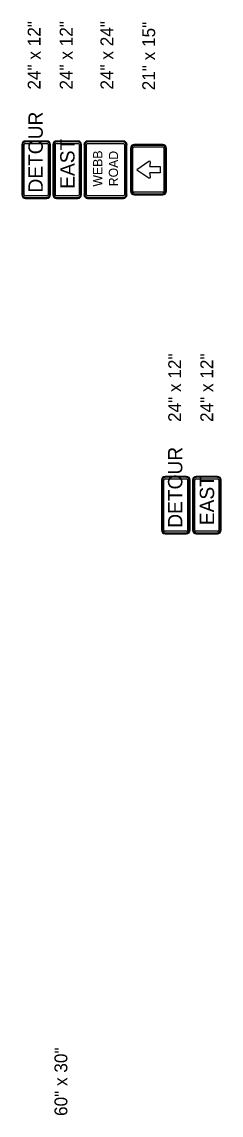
# Model space of a CAD drawing. Extents: x 1123038 to 1172987, y 554419 to 623636.
# Drawn here: x 1145939 to 1147850, y 566289 to 576781 of the extents above; entities that cross this region are included whole.
import ezdxf

# ---------------------------------------------------------------- set-up
doc = ezdxf.new("R2010")
doc.units = 0
doc.layers.add('D_Text_Standard', color=7, linetype='Continuous')
doc.layers.add('Default', color=7, linetype='Continuous')

msp = doc.modelspace()

# ---------------------------------------------------------------- linework, layer by layer
at = {"layer": 'Default'}
for p, q in [((1145939, 575603), (1145939, 575122)), ((1145947, 575603), (1145947, 575122)), ((1145962, 575122), (1145962, 575603)), ((1146179, 575637), (1145973, 575637)), ((1146179, 575629), (1145973, 575629)), ((1145973, 575614), (1146179, 575614)), ((1146191, 575603), (1146191, 575122)), ((1146205, 575122), (1146205, 575603)), ((1146214, 575122), (1146214, 575603)), ((1146237, 575603), (1146237, 575122)), ((1146245, 575603), (1146245, 575122)), ((1146260, 575122), (1146260, 575603)), ((1146477, 575637), (1146271, 575637)), ((1146477, 575629), (1146271, 575629)), ((1146271, 575614), (1146477, 575614)), ((1146489, 575603), (1146489, 575122)), ((1146503, 575122), (1146503, 575603)), ((1146512, 575122), (1146512, 575603)), ((1146535, 575603), (1146535, 575122)), ((1146543, 575603), (1146543, 575122)), ((1146558, 575122), (1146558, 575603)), ((1146913, 575637), (1146569, 575637)), ((1146913, 575629), (1146569, 575629)), ((1146569, 575614), (1146913, 575614)), ((1146924, 575603), (1146924, 575122)), ((1146938, 575122), (1146938, 575603)), ((1146947, 575122), (1146947, 575603)), ((1147291, 575603), (1147016, 575603)), ((1147291, 575594), (1147016, 575594)), ((1146981, 575569), (1146981, 575156)), ((1146990, 575569), (1146990, 575156)), ((1147004, 575156), (1147004, 575569)), ((1147016, 575580), (1147291, 575580)), ((1147302, 575569), (1147302, 575156)), ((1147317, 575156), (1147317, 575569)), ((1147325, 575156), (1147325, 575569)), ((1147156, 575441), (1147042, 575362)), ((1147165, 575392), (1147173, 575429)), ((1147165, 575392), (1147265, 575392)), ((1147265, 575392), (1147265, 575332)), ((1147042, 575362), (1147156, 575284)), ((1147173, 575296), (1147165, 575332)), ((1147265, 575332), (1147165, 575332)), ((1146179, 575110), (1145973, 575110)), ((1145973, 575096), (1146179, 575096)), ((1145973, 575087), (1146179, 575087)), ((1146477, 575110), (1146271, 575110)), ((1146271, 575096), (1146477, 575096)), ((1146271, 575087), (1146477, 575087)), ((1146913, 575110), (1146569, 575110)), ((1146569, 575096), (1146913, 575096)), ((1146569, 575087), (1146913, 575087)), ((1147291, 575145), (1147016, 575145)), ((1147016, 575130), (1147291, 575130)), ((1147016, 575122), (1147291, 575122)), ((1147277, 572384), (1147277, 571903)), ((1147286, 572384), (1147286, 571903)), ((1147300, 571903), (1147300, 572384)), ((1147518, 572419), (1147312, 572419)), ((1147518, 572410), (1147312, 572410)), ((1147312, 572396), (1147518, 572396)), ((1147529, 572384), (1147529, 571903)), ((1147544, 571903), (1147544, 572384)), ((1147552, 571903), (1147552, 572384)), ((1147575, 572384), (1147575, 571903)), ((1147584, 572384), (1147584, 571903)), ((1147598, 571903), (1147598, 572384)), ((1147816, 572419), (1147610, 572419)), ((1147816, 572410), (1147610, 572410)), ((1147610, 572396), (1147816, 572396)), ((1147827, 572384), (1147827, 571903)), ((1147842, 571903), (1147842, 572384)), ((1147850, 571903), (1147850, 572384)), ((1147518, 571892), (1147312, 571892)), ((1147312, 571877), (1147518, 571877)), ((1147312, 571869), (1147518, 571869)), ((1147816, 571892), (1147610, 571892)), ((1147610, 571877), (1147816, 571877)), ((1147610, 571869), (1147816, 571869))]:
    msp.add_line(p, q, dxfattribs=at)
for centre, radius, start, end in [((1145973, 575603), 34.4, 90, 180), ((1145973, 575603), 25.8, 90, 180), ((1145973, 575603), 11.5, 90, 180), ((1146179, 575603), 34.4, 0, 90), ((1146179, 575603), 25.8, 0, 90), ((1146179, 575603), 11.5, 0, 90), ((1146271, 575603), 34.4, 90, 180), ((1146271, 575603), 25.8, 90, 180), ((1146271, 575603), 11.5, 90, 180), ((1146477, 575603), 34.4, 0, 90), ((1146477, 575603), 25.8, 0, 90), ((1146477, 575603), 11.5, 0, 90), ((1146569, 575603), 34.4, 90, 180), ((1146569, 575603), 25.8, 90, 180), ((1146569, 575603), 11.5, 90, 180), ((1146913, 575603), 34.4, 0, 90), ((1146913, 575603), 25.8, 0, 90), ((1146913, 575603), 11.5, 0, 90), ((1147016, 575569), 34.4, 90, 180), ((1147016, 575569), 25.8, 90, 180), ((1147291, 575569), 34.4, 0, 90), ((1147291, 575569), 25.8, 0, 90), ((1147016, 575569), 11.5, 90, 180), ((1147291, 575569), 11.5, 0, 90), ((1147162, 575431), 11.5, 347.0497, 122.2757), ((1147162, 575294), 11.5, 237.7244, 12.9504), ((1145973, 575122), 34.4, 180, 270), ((1145973, 575122), 25.8, 180, 270), ((1145973, 575122), 11.5, 180, 270), ((1146179, 575122), 34.4, 270, 0), ((1146179, 575122), 25.8, 270, 0), ((1146179, 575122), 11.5, 270, 0), ((1146271, 575122), 34.4, 180, 270), ((1146271, 575122), 25.8, 180, 270), ((1146271, 575122), 11.5, 180, 270), ((1146477, 575122), 34.4, 270, 0), ((1146477, 575122), 25.8, 270, 0), ((1146477, 575122), 11.5, 270, 0), ((1146569, 575122), 34.4, 180, 270), ((1146569, 575122), 25.8, 180, 270), ((1146569, 575122), 11.5, 180, 270), ((1146913, 575122), 34.4, 270, 0), ((1146913, 575122), 25.8, 270, 0), ((1146913, 575122), 11.5, 270, 0), ((1147016, 575156), 34.4, 180, 270), ((1147016, 575156), 25.8, 180, 270), ((1147016, 575156), 11.5, 180, 270), ((1147291, 575156), 34.4, 270, 0), ((1147291, 575156), 25.8, 270, 0), ((1147291, 575156), 11.5, 270, 0), ((1147312, 572384), 34.4, 90, 180), ((1147312, 572384), 25.8, 90, 180), ((1147312, 572384), 11.5, 90, 180), ((1147518, 572384), 34.4, 0, 90), ((1147518, 572384), 25.8, 0, 90), ((1147518, 572384), 11.5, 0, 90), ((1147610, 572384), 34.4, 90, 180), ((1147610, 572384), 25.8, 90, 180), ((1147610, 572384), 11.5, 90, 180), ((1147816, 572384), 34.4, 0, 90), ((1147816, 572384), 25.8, 0, 90), ((1147816, 572384), 11.5, 0, 90), ((1147312, 571903), 34.4, 180, 270), ((1147312, 571903), 25.8, 180, 270), ((1147312, 571903), 11.5, 180, 270), ((1147518, 571903), 34.4, 270, 0), ((1147518, 571903), 25.8, 270, 0), ((1147518, 571903), 11.5, 270, 0), ((1147610, 571903), 34.4, 180, 270), ((1147610, 571903), 25.8, 180, 270), ((1147610, 571903), 11.5, 180, 270), ((1147816, 571903), 34.4, 270, 0), ((1147816, 571903), 25.8, 270, 0), ((1147816, 571903), 11.5, 270, 0)]:
    msp.add_arc(centre, radius, start, end, dxfattribs=at)

# ---------------------------------------------------------------- texts
at = {"layer": 'D_Text_Standard'}
for s, p in [('24" x 12"', (1146118, 576131)), ('24" x 12"', (1146425, 576131)), ('24" x 24"', (1146816, 576131)), ('21" x 15"', (1147217, 576124)), ('24" x 12"', (1147466, 572941)), ('24" x 12"', (1147774, 572941)), ('60" x 30"', (1146375, 566281))]:
    msp.add_text(s, height=123.2, rotation=90, dxfattribs=at).set_placement(p)
at = {"layer": 'Default'}
for s, height, p in [('DETOUR', 137.5, (1146139, 575143)), ('EAST', 137.5, (1146444, 575179)), ('WEBB', 88, (1146710, 575200)), ('ROAD', 88, (1146861, 575203)), ('DETOUR', 137.5, (1147478, 571926)), ('EAST', 137.5, (1147783, 571951))]:
    msp.add_text(s, height=height, rotation=90, dxfattribs=at).set_placement(p)

doc.saveas('drawing.dxf')
